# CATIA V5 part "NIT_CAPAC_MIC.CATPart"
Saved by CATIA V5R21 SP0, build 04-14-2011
Part number: NIT MIC
Publications: "Mating Face", "Axis"
Bounding box of the stored display mesh (mm): x -35.5 to 6.58, y -7.5 to 7.5, z -8.66 to 8.66
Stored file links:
  C:\Users\MIRCEA\Desktop\MOM\Mogan\model\NIT_CAPAC_MIC.CATPart
  C:\Program Files (x86)\Dassault Systemes\B21\intel_a\startup\components\MechanicalStandardParts\EN_Standards\Design_Tables\EN_ISO_4014_GRADES_A_B_HEXAGON_HEAD_BOLT.txt
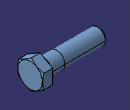
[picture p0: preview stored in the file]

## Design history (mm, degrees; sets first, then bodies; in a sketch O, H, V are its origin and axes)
Parameters
  d_dia = 10 mm
  l_length = 35.5 mm
  s_nom_across_flats = 15 mm
  k_max_head_depth = 6.58 mm
  dw_min = 14.5 mm
  r_min = 0.4 mm
  c_max = 0.6 mm
  p_pitch = 1.5 mm
  threading = 26 mm
Body1 "PartBody" (main body)
  Sketch1 on yz-plane, origin (0, 0, 0), H (0, 1, 0), V (0, 0, 1)
    circle A1 centre (0, 0) radius 7.25
    radius A1 = 7.25 {= dw_min /2}
  Pad1: profile Sketch1, direction (1, 0, 0), length 0.6 {= c_max}
  Sketch2 on face of Pad1, origin (0.6, 0, 0), H (0, 1, 0), V (0, 0, 1)
    point P1 (7.5, -4.3301)
    point P2 (7.5, 4.3301)
    point P3 (0, 8.6603)
    point P4 (-7.5, 4.3301)
    point P5 (-7.5, -4.3301)
    point P6 (0, -8.6603)
    point P7 (7.5, 0)
    line L1 (7.5, -4.3301) -> (7.5, 4.3301)
    line L2 (7.5, 4.3301) -> (0, 8.6603)
    line L3 (0, 8.6603) -> (-7.5, 4.3301)
    line L4 (-7.5, 4.3301) -> (-7.5, -4.3301)
    line L5 (-7.5, -4.3301) -> (0, -8.6603)
    line L6 (0, -8.6603) -> (7.5, -4.3301)
    construction line L7 (0, 0) -> (7.5, 0)
    construction circle A1 centre (0, 0) radius 8.6603
    construction arc A2 centre (-7.5, -4.3301) radius 8.6603 from (-7.5, 4.3301) to (0, -8.6603) cw
    construction arc A3 centre (7.5, 4.3301) radius 8.6603 from (0, 8.6603) to (7.5, -4.3301) ccw
    point P8 (-7.5, -4.3301)
    point P9 (7.5, 4.3301)
    distance L1 L4 = 15 {= s_nom_across_flats}
    horizontal: L7 H
    coincidence: A1 P1, A1 P2, A1 P3, A1 P4, A1 P5, A1 P6, A2 P4, A2 P6, A2 O, P8 P5, A3 P3, A3 P1, A3 O, P9 P2
    midpoint: P7 L1
  Pad2: profile Sketch2, direction (1, 0, 0), length 5.98 {= k_max_head_depth -c_max}
  Sketch3 on zx-plane, origin (0, 0, 0), H (-1, 0, 0), V (0, 0, 1)
    point P1 (-6.58, 7.4664)
    axis line L1 (-94.6904, 0) -> (76.7146, 0)
    reference intersected line E1 through (1000000, 0) direction (-1, 0) from xy-plane
    line L2 (-5.8907, 8.6603) -> (-6.58, 7.4664)
    line L3 (-5.8907, 8.6603) -> (-6.58, 8.6603)
    line L4 (-6.58, 8.6603) -> (-6.58, 7.4664)
    reference projected line E2 (-0.8, 8.6603) -> (-18.28, 8.6603) from edge [face of Pad2 | face of Pad2]
    distance P1 H = 7.4664 {= s_nom_across_flats /2.009}
    distance P1 V = 6.58 {= k_max_head_depth}
    angle L4 L2 = 30
    horizontal: L1 H, L3 H
    coincidence: L1 E1, L3 E2
    vertical: L4 V
  Groove1: profile Sketch3, axis Sketch3.L1, angle 360
  Sketch4 on face of Pad1, origin (0, 0, 0), H (0, -1, 0), V (0, 0, 1)
    circle A1 centre (0, 0) radius 5
    radius A1 = 5 {= d_dia /2}
  Pad3: profile Sketch4, direction (-1, 0, 0), length 9.5 {= l_length -threading}
  Sketch5 on face of Pad3, origin (-9.5, 0, 0), H (0, -1, 0), V (0, 0, 1)
    circle A1 centre (0, 0) radius 4.878
    radius A1 = 4.878 {= d_dia /2.05}
  Pad4: profile Sketch5, direction (-1, 0, 0), length 26 {= threading}
  Chamfer1: length 1.5 {= p_pitch}, angle 45, on face of Pad4
  Fillet1: radius 0.4 {= r_min}, on edge [face of Pad3 | face of Pad1]
  Thread1: diameter 9.7561 {= d_dia /1.025}, depth 26 {= threading}, pitch 1, on face of Pad4, from face of Pad4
